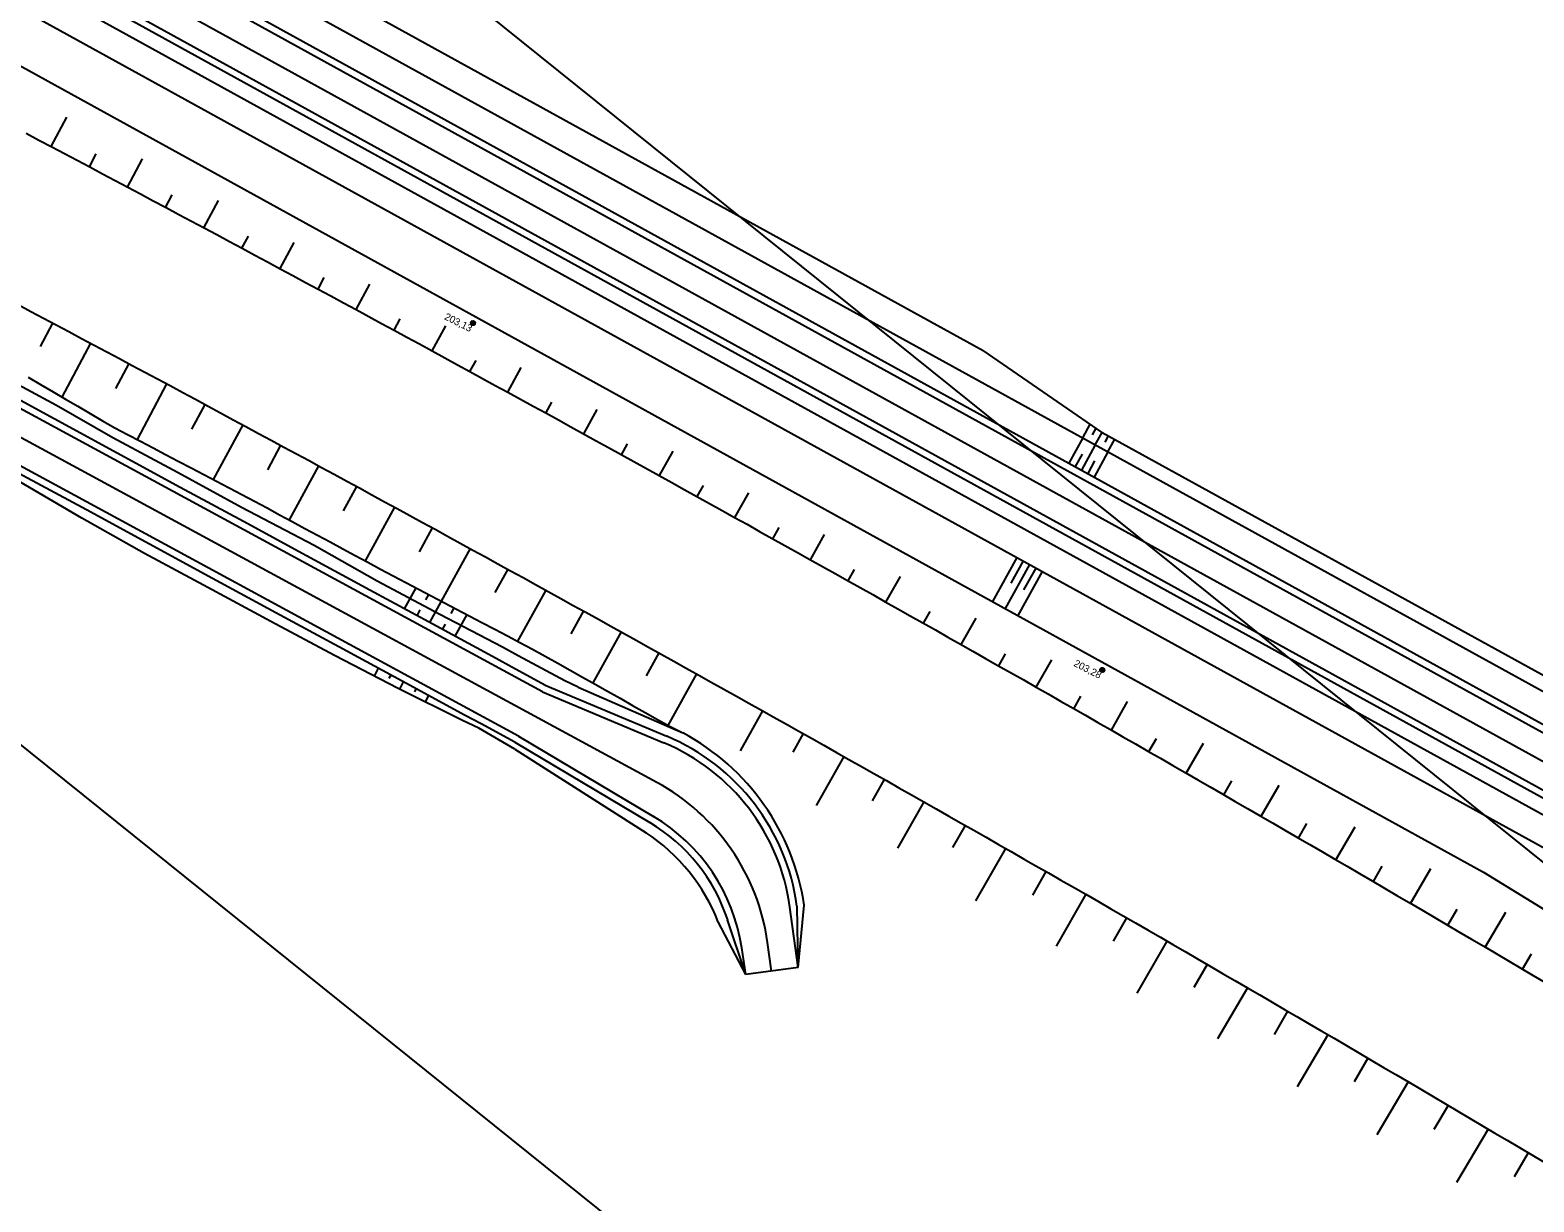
# Model space of a CAD drawing. Extents: x -551750 to -547457, y -1150683 to -1148508.
# Drawn here: x -550445.6 to -550341, y -1149017.9 to -1148936.3 of the extents above; entities that cross this region are included whole.
import ezdxf

# ---------------------------------------------------------------- set-up
doc = ezdxf.new("R2010")
doc.units = 0
for name, color, linetype in [('SO221815_VYSKOPIS', 7, 'Continuous'), ('u_ochranne_pasmo_CD', 7, 'Continuous'), ('u_trat navrh', 7, 'Continuous')]:
    doc.layers.add(name, color=color, linetype=linetype)

# ---------------------------------------------------------------- blocks, each defined once
blk = doc.blocks.new('SO221824_VYSKOPIS')
at = {"layer": 'SO221815_VYSKOPIS'}
for p, q in [((0.12, -0.09), (-0.12, 0.09)), ((0.09, 0.12), (-0.09, -0.12)), ((0.09, 0.12), (0, 0)), ((0, 0), (0.12, -0.09))]:
    blk.add_line(p, q, dxfattribs=at)
blk.add_lwpolyline([(-0.09, -0.12), (0, 0), (-0.12, 0.09)], dxfattribs=at)
blk.add_circle((0, 0), 0.15, dxfattribs=at)
for start, end in [(145.362, 235.1538), (325.362, 55.1538)]:
    blk.add_arc((0, 0), 0.15, start, end, dxfattribs=at)

msp = doc.modelspace()

# ---------------------------------------------------------------- linework, layer by layer
at = {"layer": 'u_ochranne_pasmo_CD'}
for points in [[(-551198.31, -1148574.14), (-551162.46, -1148570.35), (-551130.35, -1148568.57), (-551092.37, -1148568.39), (-551061.86, -1148569.28), (-551024.85, -1148573.11), (-550994.97, -1148578.18), (-550959.39, -1148587.7), (-550931.82, -1148595.92), (-550912.51, -1148602.68), (-550895.52, -1148609.67), (-550856.33, -1148625.77), (-550813.03, -1148648.94), (-550764.5, -1148678.6), (-550612.94, -1148787.03), (-550541.96, -1148842.17), (-550442.34, -1148912.27), (-550342.72, -1148992.32), (-550298.52, -1149027.84), (-550206.09, -1149095.14), (-550118.21, -1149167.54), (-550033.18, -1149228.92)], [(-551192.01, -1148633.8), (-551157.64, -1148630.18), (-551128.55, -1148628.56), (-551093.1, -1148628.4), (-551065.82, -1148629.19), (-551032.97, -1148632.59), (-551007.77, -1148636.86), (-550975.72, -1148645.44), (-550950.32, -1148653.02), (-550933.85, -1148658.78), (-550881.95, -1148680.12), (-550842.85, -1148701.03), (-550797.65, -1148728.66), (-550648.81, -1148835.14), (-550577.65, -1148890.43), (-550478.43, -1148960.24), (-550334.99, -1149075.5), (-550242.86, -1149142.59), (-550154.88, -1149215.07), (-550068.29, -1149277.57)]]:
    msp.add_lwpolyline(points, dxfattribs=at)
at = {"layer": 'u_trat navrh'}
for p, q in [((-550460.23, -1148921.16), (-550253.98, -1149034.78)), ((-550461.07, -1148922.69), (-550254.82, -1149036.32)), ((-550461.8, -1148924.01), (-550255.55, -1149037.63)), ((-550440.69, -1148924.79), (-550379.29, -1148958.62)), ((-550462.76, -1148925.76), (-550256.51, -1149039.38)), ((-550441.65, -1148926.54), (-550251.93, -1149031.06)), ((-550442.86, -1148928.73), (-550253.14, -1149033.25)), ((-550442.62, -1148928.29), (-550252.89, -1149032.81)), ((-550464.45, -1148928.82), (-550344.48, -1148994.92)), ((-550409.97, -1148982.38), (-550489.88, -1148939.06)), ((-550411.64, -1148985.46), (-550491.54, -1148942.14)), ((-550444.16, -1148944.43), (-550443.07, -1148942.38)), ((-550441.5, -1148945.84), (-550441.02, -1148944.94)), ((-550438.84, -1148947.25), (-550437.8, -1148945.29)), ((-550436.19, -1148948.66), (-550435.73, -1148947.8)), ((-550433.53, -1148950.08), (-550432.52, -1148948.19)), ((-550430.88, -1148951.5), (-550430.43, -1148950.67)), ((-550428.23, -1148952.92), (-550427.25, -1148951.1)), ((-550425.58, -1148954.35), (-550425.15, -1148953.54)), ((-550422.94, -1148955.78), (-550421.98, -1148954)), ((-550444.06, -1148956.71), (-550444.93, -1148958.35)), ((-550420.29, -1148957.21), (-550419.86, -1148956.42)), ((-550417.65, -1148958.65), (-550416.7, -1148956.91)), ((-550441.41, -1148958.12), (-550443.41, -1148961.86)), ((-550371.01, -1148964.32), (-550379.29, -1148958.62)), ((-550438.76, -1148959.53), (-550439.69, -1148961.26)), ((-550415.01, -1148960.09), (-550414.59, -1148959.31)), ((-550412.38, -1148961.53), (-550411.44, -1148959.81)), ((-550436.12, -1148960.95), (-550438.18, -1148964.81)), ((-550409.73, -1148962.98), (-550409.31, -1148962.21)), ((-550433.47, -1148962.37), (-550434.4, -1148964.09)), ((-550407.09, -1148964.43), (-550406.16, -1148962.72)), ((-550430.83, -1148963.79), (-550432.88, -1148967.6)), ((-550372.37, -1148964.71), (-550371.84, -1148963.75)), ((-550371.68, -1148964.49), (-550371.42, -1148964.03)), ((-550371.49, -1148965.19), (-550371.01, -1148964.32)), ((-550371.01, -1148964.32), (-550251.45, -1149030.19)), ((-550428.19, -1148965.22), (-550429.1, -1148966.92)), ((-550404.46, -1148965.88), (-550404.04, -1148965.11)), ((-550372.37, -1148964.71), (-550373.33, -1148966.46)), ((-550371.49, -1148965.19), (-550372.46, -1148966.95)), ((-550370.81, -1148965), (-550370.57, -1148964.56)), ((-550370.62, -1148965.68), (-550370.13, -1148964.8)), ((-550401.83, -1148967.33), (-550400.88, -1148965.63)), ((-550372.41, -1148965.83), (-550372.9, -1148966.7)), ((-550371.54, -1148966.31), (-550372.02, -1148967.19)), ((-550370.62, -1148965.68), (-550371.58, -1148967.43)), ((-550425.55, -1148966.65), (-550427.59, -1148970.41)), ((-550422.91, -1148968.08), (-550423.83, -1148969.77)), ((-550399.2, -1148968.79), (-550398.77, -1148968.02)), ((-550396.57, -1148970.25), (-550395.61, -1148968.53)), ((-550420.27, -1148969.52), (-550422.31, -1148973.26)), ((-550417.64, -1148970.96), (-550418.55, -1148972.63)), ((-550393.94, -1148971.72), (-550393.5, -1148970.94)), ((-550391.31, -1148973.18), (-550390.34, -1148971.44)), ((-550415, -1148972.4), (-550417.01, -1148976.07)), ((-550376.95, -1148973.03), (-550378.64, -1148976.1)), ((-550376.08, -1148973.51), (-550377.77, -1148976.58)), ((-550376.51, -1148973.27), (-550377.36, -1148974.81)), ((-550375.64, -1148973.76), (-550376.48, -1148975.29)), ((-550412.37, -1148973.85), (-550413.27, -1148975.47)), ((-550388.69, -1148974.66), (-550388.24, -1148973.86)), ((-550386.07, -1148976.13), (-550385.06, -1148974.34)), ((-550375.2, -1148974), (-550376.89, -1148977.06)), ((-550418.79, -1148975.14), (-550419.58, -1148976.6)), ((-550417.9, -1148975.6), (-550418.1, -1148975.97)), ((-550409.74, -1148975.3), (-550411.7, -1148978.85)), ((-550418.49, -1148976.68), (-550418.7, -1148977.08)), ((-550417.01, -1148976.07), (-550417.82, -1148977.55)), ((-550416.13, -1148976.53), (-550416.34, -1148976.92)), ((-550407.12, -1148976.75), (-550408, -1148978.34)), ((-550383.45, -1148977.61), (-550382.99, -1148976.79)), ((-550416.74, -1148977.66), (-550416.94, -1148978.03)), ((-550415.24, -1148977), (-550416.06, -1148978.51)), ((-550380.83, -1148979.09), (-550379.79, -1148977.25)), ((-550404.49, -1148978.21), (-550406.46, -1148981.76)), ((-550401.87, -1148979.66), (-550402.76, -1148981.27)), ((-550378.21, -1148980.57), (-550377.74, -1148979.73)), ((-550421.4, -1148980.73), (-550421.69, -1148981.28)), ((-550399.24, -1148981.13), (-550401.24, -1148984.71)), ((-550375.6, -1148982.06), (-550374.51, -1148980.15)), ((-550420.53, -1148981.21), (-550420.66, -1148981.46)), ((-550419.65, -1148981.68), (-550419.91, -1148982.2)), ((-550418.77, -1148982.16), (-550418.88, -1148982.38)), ((-550409.78, -1148981.92), (-550401.32, -1148985.47)), ((-550407.48, -1148982.06), (-550400.2, -1148985.24)), ((-550417.89, -1148982.64), (-550418.12, -1148983.08)), ((-550409.97, -1148982.38), (-550401.51, -1148985.93)), ((-550372.99, -1148983.55), (-550372.49, -1148982.67)), ((-550370.37, -1148985.04), (-550369.24, -1148983.06)), ((-550394.65, -1148983.7), (-550396.21, -1148986.48)), ((-550391.82, -1148985.28), (-550392.55, -1148986.58)), ((-550411.9, -1148985.89), (-550402.5, -1148991.48)), ((-550411.64, -1148985.46), (-550402.24, -1148991.05)), ((-550367.76, -1148986.54), (-550367.24, -1148985.63)), ((-550365.16, -1148988.04), (-550363.96, -1148985.96)), ((-550411.9, -1148986.37), (-550402.75, -1148992.18)), ((-550389, -1148986.87), (-550390.92, -1148990.28)), ((-550386.18, -1148988.47), (-550387.02, -1148989.96)), ((-550362.55, -1148989.54), (-550362, -1148988.58)), ((-550359.95, -1148991.04), (-550358.69, -1148988.87)), ((-550383.42, -1148990.03), (-550385.25, -1148993.25)), ((-550357.34, -1148992.55), (-550356.76, -1148991.55)), ((-550380.55, -1148991.67), (-550381.43, -1148993.22)), ((-550354.74, -1148994.06), (-550353.41, -1148991.78)), ((-550377.74, -1148993.27), (-550379.82, -1148996.92)), ((-550352.14, -1148995.58), (-550351.53, -1148994.52)), ((-550349.55, -1148997.1), (-550348.14, -1148994.68)), ((-550374.93, -1148994.88), (-550375.87, -1148996.52)), ((-550344.48, -1148994.92), (-550325.74, -1149006.5)), ((-550372.15, -1148996.47), (-550374.22, -1149000.07)), ((-550392.18, -1149001.56), (-550392.75, -1148997.37)), ((-550392.18, -1149001.56), (-550392.25, -1148997.3)), ((-550392.18, -1149001.56), (-550391.76, -1148997.23)), ((-550346.95, -1148998.62), (-550346.3, -1148997.5)), ((-550344.36, -1149000.14), (-550342.93, -1148997.71)), ((-550395.82, -1149002.06), (-550397.73, -1148998.39)), ((-550395.82, -1149002.06), (-550397.08, -1148998.24)), ((-550369.31, -1148998.11), (-550370.25, -1148999.74)), ((-550366.51, -1148999.72), (-550368.6, -1149003.35)), ((-550395.82, -1149002.06), (-550396.1, -1149000.19)), ((-550341.77, -1149001.67), (-550341.14, -1149000.6)), ((-550392.18, -1149001.56), (-550395.82, -1149002.06)), ((-550363.7, -1149001.35), (-550364.64, -1149002.96)), ((-550360.91, -1149002.97), (-550362.98, -1149006.52)), ((-550358.11, -1149004.6), (-550359.05, -1149006.23)), ((-550355.31, -1149006.24), (-550357.44, -1149009.87)), ((-550352.52, -1149007.87), (-550353.48, -1149009.52)), ((-550349.72, -1149009.52), (-550351.9, -1149013.21)), ((-550346.93, -1149011.16), (-550347.92, -1149012.83)), ((-550344.15, -1149012.81), (-550346.35, -1149016.53)), ((-550341.36, -1149014.46), (-550342.35, -1149016.12))]:
    msp.add_line(p, q, dxfattribs=at)
for points in [[(-550255.07, -1149036.76), (-550461.31, -1148923.13)], [(-550409.76, -1148981.93), (-550412.1, -1148980.66), (-550413.19, -1148980.06), (-550417.59, -1148977.68), (-550421.99, -1148975.3), (-550426.38, -1148972.91), (-550430.78, -1148970.53), (-550435.17, -1148968.15), (-550439.57, -1148965.77), (-550443.96, -1148963.38), (-550448.36, -1148961), (-550452.75, -1148958.62), (-550457.15, -1148956.23), (-550461.55, -1148953.85), (-550465.94, -1148951.47), (-550470.34, -1148949.08), (-550474.73, -1148946.7), (-550479.13, -1148944.32), (-550483.52, -1148941.94), (-550487.92, -1148939.55), (-550489.64, -1148938.62)], [(-550407.48, -1148982.06), (-550408.4, -1148981.62), (-550411.66, -1148979.87), (-550412.75, -1148979.26), (-550417.11, -1148977), (-550421.46, -1148974.67), (-550425.85, -1148972.19), (-550430.92, -1148969.55), (-550435.33, -1148967.13), (-550439.86, -1148964.71), (-550443.79, -1148962.45), (-550447.95, -1148960.23), (-550452.36, -1148957.89), (-550456.72, -1148955.46), (-550461.09, -1148953.02), (-550466.15, -1148950.59), (-550470.65, -1148948.19), (-550474.34, -1148946.2), (-550478.82, -1148943.72), (-550483.28, -1148941.36), (-550487.6, -1148939), (-550488.45, -1148938.49)], [(-550402.01, -1148988.68), (-550490.71, -1148940.6)], [(-550411.9, -1148986.37), (-550414.4, -1148984.91), (-550415.53, -1148984.37), (-550420.01, -1148982.15), (-550424.45, -1148979.85), (-550428.86, -1148977.48), (-550433.26, -1148975.12), (-550437.66, -1148972.74), (-550442.03, -1148970.3), (-550446.34, -1148967.77), (-550450.66, -1148965.25), (-550455.07, -1148962.89), (-550459.47, -1148960.52), (-550463.93, -1148958.25), (-550468.35, -1148955.91), (-550472.66, -1148953.38), (-550476.99, -1148950.86), (-550481.3, -1148948.33), (-550485.68, -1148945.91), (-550490.1, -1148943.58), (-550491.84, -1148942.68)], [(-550411.89, -1148985.89), (-550414.24, -1148984.61), (-550415.34, -1148984.02), (-550419.73, -1148981.64), (-550424.13, -1148979.25), (-550428.53, -1148976.87), (-550432.92, -1148974.49), (-550437.32, -1148972.1), (-550441.71, -1148969.72), (-550446.11, -1148967.34), (-550450.5, -1148964.96), (-550454.9, -1148962.57), (-550459.29, -1148960.19), (-550463.69, -1148957.81), (-550468.09, -1148955.42), (-550472.48, -1148953.04), (-550476.88, -1148950.66), (-550481.27, -1148948.27), (-550485.67, -1148945.89), (-550490.06, -1148943.51), (-550491.78, -1148942.58)], [(-550445.89, -1148943.51), (-550445.01, -1148943.98), (-550444.12, -1148944.45), (-550443.24, -1148944.92), (-550442.35, -1148945.38), (-550441.47, -1148945.85), (-550440.58, -1148946.32), (-550439.7, -1148946.79), (-550438.82, -1148947.26), (-550437.93, -1148947.73), (-550437.05, -1148948.2), (-550436.16, -1148948.67), (-550435.28, -1148949.15), (-550434.4, -1148949.62), (-550433.51, -1148950.09), (-550432.63, -1148950.56), (-550431.75, -1148951.04), (-550430.87, -1148951.51), (-550429.98, -1148951.98), (-550429.1, -1148952.46), (-550428.22, -1148952.93), (-550427.34, -1148953.4), (-550426.46, -1148953.88), (-550425.57, -1148954.35), (-550424.69, -1148954.83), (-550423.81, -1148955.31), (-550422.93, -1148955.78), (-550422.05, -1148956.26), (-550421.17, -1148956.74), (-550420.29, -1148957.21), (-550419.41, -1148957.69), (-550418.53, -1148958.17), (-550417.65, -1148958.65), (-550416.77, -1148959.13), (-550415.89, -1148959.61), (-550415.01, -1148960.09), (-550414.13, -1148960.57), (-550413.26, -1148961.05), (-550412.38, -1148961.53), (-550411.5, -1148962.01), (-550410.62, -1148962.49), (-550409.74, -1148962.97), (-550408.86, -1148963.45), (-550407.99, -1148963.93), (-550407.11, -1148964.42), (-550406.23, -1148964.9), (-550405.36, -1148965.38), (-550404.48, -1148965.87), (-550403.6, -1148966.35), (-550402.73, -1148966.84), (-550401.85, -1148967.32), (-550400.97, -1148967.81), (-550400.1, -1148968.29), (-550399.22, -1148968.78), (-550398.35, -1148969.26), (-550397.47, -1148969.75), (-550396.6, -1148970.24), (-550395.72, -1148970.72), (-550394.85, -1148971.21), (-550393.97, -1148971.7), (-550393.1, -1148972.19), (-550392.22, -1148972.68), (-550391.35, -1148973.16), (-550390.48, -1148973.65), (-550389.6, -1148974.14), (-550388.73, -1148974.63), (-550387.86, -1148975.12), (-550386.98, -1148975.61), (-550386.11, -1148976.11), (-550385.24, -1148976.6), (-550384.37, -1148977.09), (-550383.49, -1148977.58), (-550382.62, -1148978.07), (-550381.75, -1148978.57), (-550380.88, -1148979.06), (-550380.01, -1148979.55), (-550379.14, -1148980.05), (-550378.27, -1148980.54), (-550377.4, -1148981.04), (-550376.52, -1148981.53), (-550375.65, -1148982.03), (-550374.78, -1148982.52), (-550373.91, -1148983.02), (-550373.04, -1148983.51), (-550372.18, -1148984.01), (-550371.31, -1148984.51), (-550370.44, -1148985), (-550369.57, -1148985.5), (-550368.7, -1148986), (-550367.83, -1148986.5), (-550366.96, -1148987), (-550366.09, -1148987.5), (-550365.23, -1148988), (-550364.36, -1148988.5), (-550363.49, -1148989), (-550362.62, -1148989.5), (-550361.76, -1148990), (-550360.89, -1148990.5), (-550360.02, -1148991), (-550359.16, -1148991.5), (-550358.29, -1148992), (-550357.42, -1148992.51), (-550356.56, -1148993.01), (-550355.69, -1148993.51), (-550354.83, -1148994.02), (-550353.96, -1148994.52), (-550353.1, -1148995.02), (-550352.23, -1148995.53), (-550351.37, -1148996.03), (-550350.5, -1148996.54), (-550349.64, -1148997.04), (-550348.77, -1148997.55), (-550347.91, -1148998.06), (-550347.05, -1148998.56), (-550346.18, -1148999.07), (-550345.32, -1148999.58), (-550344.46, -1149000.08), (-550343.59, -1149000.59), (-550342.73, -1149001.1), (-550341.87, -1149001.61), (-550341.01, -1149002.12), (-550340.14, -1149002.63)], [(-550446.46, -1148955.43), (-550445.58, -1148955.9), (-550444.69, -1148956.37), (-550443.81, -1148956.84), (-550442.93, -1148957.31), (-550442.05, -1148957.78), (-550441.17, -1148958.25), (-550440.29, -1148958.72), (-550439.41, -1148959.19), (-550438.52, -1148959.66), (-550437.64, -1148960.13), (-550436.76, -1148960.6), (-550435.88, -1148961.07), (-550435, -1148961.54), (-550434.12, -1148962.02), (-550433.24, -1148962.49), (-550432.37, -1148962.96), (-550431.49, -1148963.44), (-550430.61, -1148963.91), (-550429.73, -1148964.39), (-550428.85, -1148964.86), (-550427.97, -1148965.34), (-550427.09, -1148965.81), (-550426.21, -1148966.29), (-550425.34, -1148966.76), (-550424.46, -1148967.24), (-550423.58, -1148967.72), (-550422.7, -1148968.19), (-550421.83, -1148968.67), (-550420.95, -1148969.15), (-550420.07, -1148969.63), (-550419.2, -1148970.11), (-550418.32, -1148970.59), (-550417.44, -1148971.06), (-550416.57, -1148971.54), (-550415.69, -1148972.02), (-550414.82, -1148972.51), (-550413.94, -1148972.99), (-550413.07, -1148973.47), (-550412.19, -1148973.95), (-550411.32, -1148974.43), (-550410.44, -1148974.91), (-550409.57, -1148975.39), (-550408.69, -1148975.88), (-550407.82, -1148976.36), (-550406.95, -1148976.84), (-550406.07, -1148977.33), (-550405.2, -1148977.81), (-550404.32, -1148978.3), (-550403.45, -1148978.78), (-550402.58, -1148979.27), (-550401.71, -1148979.75), (-550400.83, -1148980.24), (-550399.96, -1148980.73), (-550399.09, -1148981.21), (-550398.22, -1148981.7), (-550397.35, -1148982.19), (-550396.47, -1148982.67), (-550395.6, -1148983.16), (-550394.73, -1148983.65), (-550393.86, -1148984.14), (-550392.99, -1148984.63), (-550392.12, -1148985.12), (-550391.25, -1148985.61), (-550390.38, -1148986.1), (-550389.51, -1148986.59), (-550388.64, -1148987.08), (-550387.77, -1148987.57), (-550386.9, -1148988.06), (-550386.03, -1148988.55), (-550385.16, -1148989.05), (-550384.29, -1148989.54), (-550383.42, -1148990.03), (-550382.56, -1148990.52), (-550381.69, -1148991.02), (-550380.82, -1148991.51), (-550379.95, -1148992.01), (-550379.08, -1148992.5), (-550378.22, -1148993), (-550377.35, -1148993.49), (-550376.48, -1148993.99), (-550375.62, -1148994.48), (-550374.75, -1148994.98), (-550373.88, -1148995.48), (-550373.02, -1148995.97), (-550372.15, -1148996.47), (-550371.28, -1148996.97), (-550370.42, -1148997.47), (-550369.55, -1148997.97), (-550368.69, -1148998.46), (-550367.82, -1148998.96), (-550366.96, -1148999.46), (-550366.09, -1148999.96), (-550365.23, -1149000.46), (-550364.37, -1149000.96), (-550363.5, -1149001.47), (-550362.64, -1149001.97), (-550361.77, -1149002.47), (-550360.91, -1149002.97), (-550360.05, -1149003.47), (-550359.18, -1149003.97), (-550358.32, -1149004.48), (-550357.46, -1149004.98), (-550356.6, -1149005.48), (-550355.73, -1149005.99), (-550354.87, -1149006.49), (-550354.01, -1149007), (-550353.15, -1149007.5), (-550352.29, -1149008.01), (-550351.43, -1149008.51), (-550350.57, -1149009.02), (-550349.7, -1149009.53), (-550348.84, -1149010.03), (-550347.98, -1149010.54), (-550347.12, -1149011.05), (-550346.26, -1149011.56), (-550345.4, -1149012.06), (-550344.54, -1149012.57), (-550343.68, -1149013.08), (-550342.83, -1149013.59), (-550341.97, -1149014.1), (-550341.11, -1149014.61), (-550340.25, -1149015.12)], [(-550445.76, -1148960.49), (-550444.89, -1148961), (-550444.03, -1148961.5), (-550443.17, -1148962), (-550442.31, -1148962.5), (-550441.45, -1148963.01), (-550440.59, -1148963.51), (-550439.72, -1148964), (-550438.84, -1148964.47), (-550437.95, -1148964.93), (-550437.07, -1148965.39), (-550436.19, -1148965.86), (-550435.31, -1148966.32), (-550434.42, -1148966.79), (-550433.54, -1148967.25), (-550432.66, -1148967.72), (-550431.78, -1148968.19), (-550430.89, -1148968.64), (-550430.01, -1148969.1), (-550429.13, -1148969.58), (-550428.26, -1148970.05), (-550427.38, -1148970.53), (-550426.5, -1148971), (-550425.62, -1148971.47), (-550424.74, -1148971.94), (-550423.87, -1148972.42), (-550422.99, -1148972.89), (-550422.11, -1148973.36), (-550421.24, -1148973.84), (-550420.36, -1148974.31), (-550419.48, -1148974.78), (-550418.59, -1148975.24), (-550417.71, -1148975.7), (-550416.83, -1148976.17), (-550415.94, -1148976.63), (-550415.06, -1148977.09), (-550414.18, -1148977.55), (-550413.29, -1148978.02), (-550412.41, -1148978.48), (-550411.53, -1148978.95), (-550410.65, -1148979.41), (-550409.77, -1148979.89), (-550408.9, -1148980.38), (-550408.03, -1148980.87), (-550407.17, -1148981.36), (-550406.3, -1148981.85), (-550405.43, -1148982.34), (-550404.56, -1148982.83), (-550403.69, -1148983.32), (-550402.82, -1148983.81), (-550401.96, -1148984.3), (-550401.09, -1148984.79), (-550400.2, -1148985.24)], [(-550394.03, -1149001.81), (-550394.3, -1148999.83)]]:
    msp.add_lwpolyline(points, dxfattribs=at)
for centre, radius, start, end in [((-550407.87, -1148999.61), 16.29, 8.3983, 61.9047), ((-550407.12, -1148999.3), 14.5, 7.6621, 67.2476), ((-550407.12, -1148999.3), 15, 7.6621, 67.2476), ((-550409.16, -1149001.87), 15, 7.816, 61.537), ((-550408.81, -1149002.09), 12.35, 18.1811, 59.2464), ((-550408.81, -1149002.09), 12.85, 8.5025, 59.2464), ((-550410.26, -1149003.39), 13.49, 21.7293, 56.1545)]:
    msp.add_arc(centre, radius, start, end, dxfattribs=at)

# ---------------------------------------------------------------- block references
at = {"layer": 'u_trat navrh', "rotation": -31.851985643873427}
for p in [(-550414.8, -1148956.72), (-550371.01, -1148980.85)]:
    msp.add_blockref('SO221824_VYSKOPIS', p, dxfattribs=at)

# ---------------------------------------------------------------- texts
at = {"layer": 'u_trat navrh'}
for s, p in [('203,13', (-550416.84, -1148956.43)), ('203,28', (-550373.04, -1148980.56))]:
    msp.add_text(s, height=0.5, rotation=333.2568, dxfattribs=at).set_placement(p)

doc.saveas('drawing.dxf')
